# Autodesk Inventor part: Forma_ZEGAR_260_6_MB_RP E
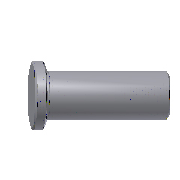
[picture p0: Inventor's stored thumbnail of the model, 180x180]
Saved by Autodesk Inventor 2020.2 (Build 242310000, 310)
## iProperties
Manager: www.cadconsulting.pl
Company: Fabian Stasiak CAD Consulting
Created: 2014-02
Part Number: Forma_ZEGAR_260_6_MB_RP E
Material: SUJ 2
Description: Return Pin
Document SubType Name: Modeling
Designer: F.Stasiak
Standard Revision: 1
Manufacturer: DME
Language: pl-PL
Size Designation: 14x132
Categories: <MemberInstance><Categories><Category DisplayName="Forma wtryskowa" InternalName="349578f2-f4d4-4954-8c09-8e99297a61c0" Mnemonic="MOLD"><Category DisplayName="K
Mass: 6.63789 g
Surface Area: 25.7048 cm^2
Volume: 6.63789 cm^3
Density: 7.85 g/cm^3
Appearance: Aluminium - ciemne
Catalog Web Link: www.expertbooks.pl
IsCustomPart: 1
Author: F.Stasiak
Subject: Zbiór ćwiczeń. Autodesk Inventor 2020. Kurs Professional
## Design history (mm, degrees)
sketch "Sketch1"
  geometry: L1 (0, -15)-(0, 62) reference; L2 (0, -4)-(9.5, -4); L3 (9.5, -4)-(9.5, 0); L4 (9.5, 0)-(7, 0); L5 (7, 0)-(7, 128); L6 (7, 128)-(0, 128); L7 (0, 128)-(0, -4); 1 further point
  constraints: 12 end point, 3 perpendicular, 2 parallel, 2 point on line, 1 collinear, 1 horizontal alignment
  dimensions: "d28" = 4 distance between parallel lines of L2 L4 (= H_); "d29" = 19 diameter of L3 L1 (= D); "d31" = 14 diameter of L5 L1 (= d_); "d33" = 132 distance between parallel lines of L2 L6 (= L)
revolve "Revolution1" sketch "Sketch1" stored, may be unused: angle "d41" = 90 deg
sketch "Sketch2"
  geometry: L1 (7, 128)-(7, 0) reference; L2 (-7, 0)-(7, 0) reference; L3 (7, 0)-(6.8, 0); L4 (6.5, 0.3)-(6.5, 0.9); L5 (6.8, 1.2)-(7, 1.2); L6 (7, 1.2)-(7, 0); L7 (0, -10.275)-(0, 61.212) reference; A1 r 0.3 centre (6.8, 0.9) between (6.8, 1.2) and (6.5, 0.9); A2 r 0.3 centre (6.8, 0.3) between (6.5, 0.3) and (6.8, 0); 1 further point
  constraints: 8 end point, 4 point on circle, 4 tangent, 2 centre point, 2 parallel, 1 equal radius, 1 horizontal, 1 perpendicular
  dimensions: "d45" = 0.3 radius of A1; "d46" = 1.2 distance between parallel lines of L2 L5; "d47" = 0.5 distance between parallel lines of L4 L1
revolve "Revolution2" sketch "Sketch2" stored, may be unused: angle "d48" = 90 deg
chamfer "Chamfer1" distance "d49" = 0.5; stored, may be unused: second distance "d50" = 2, angle "d51" = 45 deg
body "Solid1"
other parameters: "d_" = 14 [user parameter; used in 1 equation term], "L" = 132 [user parameter; used in 1 equation term], "D" = 19 [user parameter; used in 1 equation term], "H_" = 4 [user parameter; used in 1 equation term], "d44" = 0, "d52" = 0, "d53" = 0
